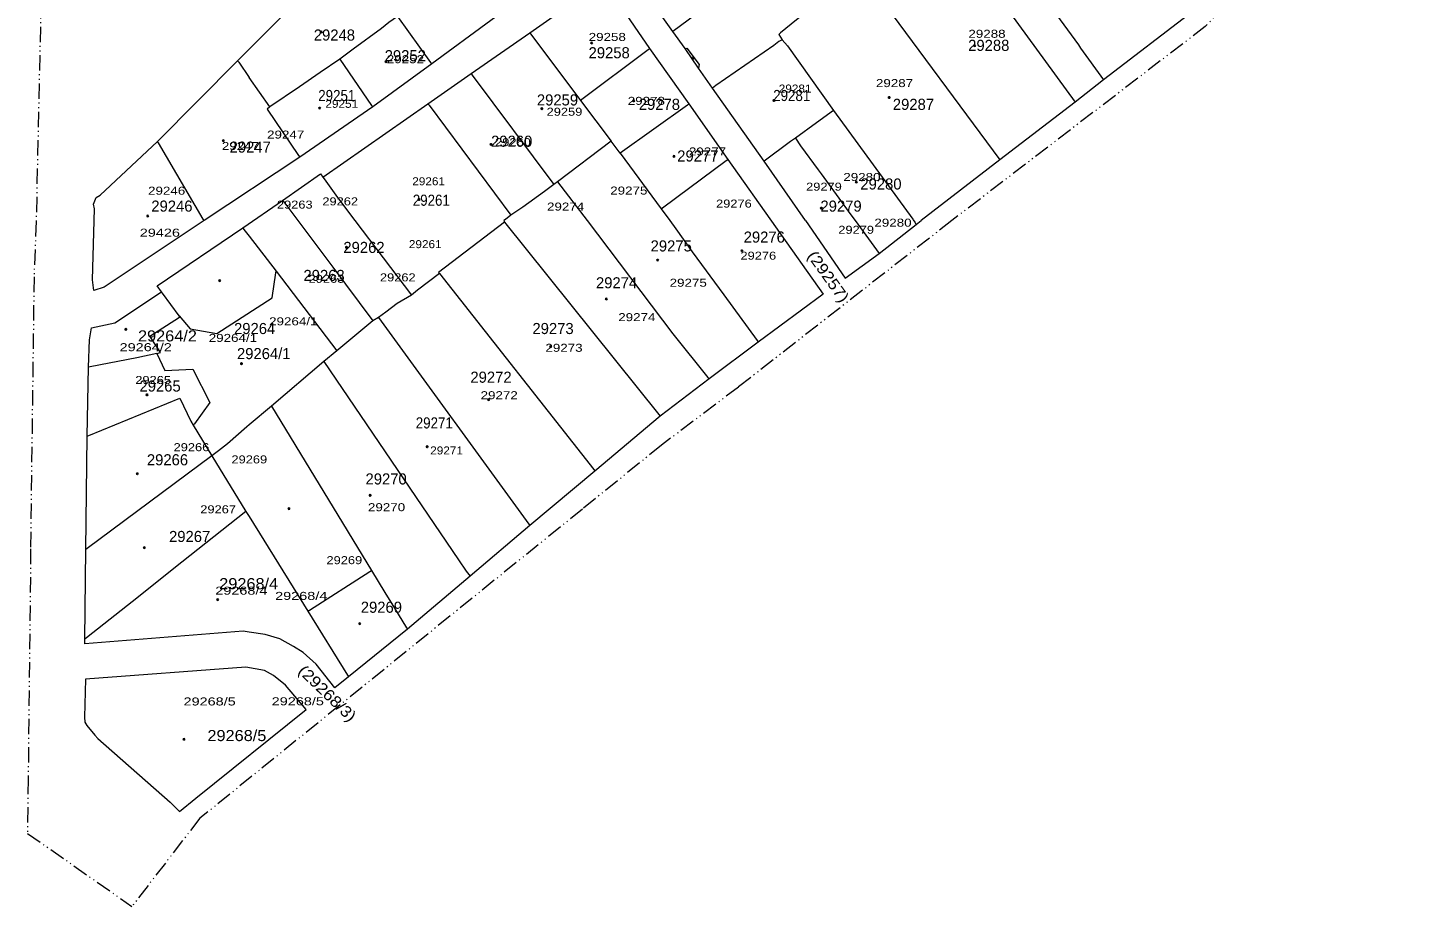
# Model space of a CAD drawing. Extents: x 650553 to 652508, y 239277 to 241647.
# Drawn here: x 650553 to 651000, y 239277.3 to 239562.7 of the extents above; entities that cross this region are included whole.
import ezdxf

# ---------------------------------------------------------------- set-up
doc = ezdxf.new("R2010")
doc.units = 0
doc.header["$PDMODE"] = 32
doc.header["$PDSIZE"] = 0.5
doc.linetypes.add('DASH_DOUBLE_DOT', pattern=[9.2, 5, -1.2, 0.3, -1.2, 0.3, -1.2])
for name, color, linetype in [('19', 7, 'Continuous'), ('20', 7, 'Continuous'), ('44', 7, 'Continuous'), ('6', 7, 'Continuous')]:
    doc.layers.add(name, color=color, linetype=linetype)
for name, color, linetype, lineweight in [('3', 7, 'Continuous', 13), ('5', 7, 'Continuous', 13), ('52', 7, 'DASH_DOUBLE_DOT', 13)]:
    doc.layers.add(name, color=color, linetype=linetype, lineweight=lineweight)

msp = doc.modelspace()

# ---------------------------------------------------------------- linework, layer by layer
at = {"layer": '3'}
msp.add_line((650770.98, 239549.48), (650766.66, 239555.85), dxfattribs=at)
for points in [[(650766.66, 239555.85), (650762.69, 239561.36), (650746.99, 239583.49), (650766.57, 239599.63), (650765.87, 239600.32), (650777.65, 239613.61), (650778.65, 239612.38), (650790.25, 239624.22), (650813.28, 239649.12), (650837.06, 239673.5), (650840.71, 239673.57), (650857.5, 239654.04), (650866.83, 239643.35), (650876.22, 239632.41), (650885.67, 239621.34), (650903.75, 239600.18), (650931.7, 239568.01), (650902.59, 239545.65), (650893.39, 239538.45), (650868.88, 239519.76), (650843.34, 239500)], [(650718.04, 239599.25), (650729.3, 239584.51), (650729.19, 239583.87), (650703.5, 239564.91), (650684.32, 239550.84), (650665.13, 239536.9), (650641.42, 239520.61), (650610.36, 239500)], [(650574.582, 239477.239), (650574.134, 239480.709), (650574.717, 239503.811), (650574.49, 239505.368), (650574.913, 239506.43), (650575.36, 239507.491), (650576.588, 239508.285), (650595.268, 239525.716), (650621.254, 239551.909), (650654.66, 239585.53)], [(650716.19, 239560.97), (650738.16, 239576.42), (650741.28, 239575.98), (650755.11, 239555.85), (650767.89, 239537.86), (650780.51, 239519.85), (650811.5, 239476.07)], [(650635.87, 239506.54), (650648.23, 239515.14), (650648.99, 239514.09), (650683.06, 239537.92), (650697.11, 239547.7), (650716.19, 239560.97)], [(650805.69, 239500), (650792.32, 239519.26), (650775.57, 239542.95), (650770.98, 239549.48)], [(650596.53, 239476.9), (650595.13, 239478.77), (650622.94, 239497.63), (650635.87, 239506.54)], [(650610.36, 239500), (650577.916, 239478.38), (650574.582, 239477.239)], [(650805.69, 239500), (650818.67, 239481.31), (650829.71, 239489.27), (650841.71, 239498.74), (650843.34, 239500)], [(650572.85, 239452.4), (650573.17, 239461.27), (650573.827, 239465.187), (650581.417, 239466.74), (650596.53, 239476.9)], [(650811.5, 239476.07), (650790.35, 239460.51), (650774.42, 239448.55), (650758.49, 239436.51), (650737.35, 239418.67), (650716.22, 239400.93), (650696.77, 239384.52), (650676.41, 239367.3), (650657.3, 239351.86)], [(650657.3, 239351.86), (650652.84, 239348.24), (650646.78, 239355.91), (650642.52, 239359.72), (650639.36, 239361.66), (650635, 239364.16), (650630.24, 239365.64), (650625, 239366.37), (650623.07, 239366.64), (650571.62, 239362.51), (650571.63, 239364.07), (650571.93, 239393.18), (650572.42, 239429.99), (650572.85, 239452.4)], [(650643.51, 239341.28), (650636.83, 239349.19), (650632.92, 239352.23), (650629.96, 239353.91), (650623.98, 239354.96), (650571.791, 239351.034), (650571.564, 239338.794), (650571.637, 239337.113), (650572.328, 239336.032), (650574.908, 239332.935), (650575.851, 239331.85), (650599.36, 239311.1), (650602.39, 239308.17)], [(650602.39, 239308.17), (650607.67, 239312.43), (650643.51, 239341.28)]]:
    msp.add_lwpolyline(points, dxfattribs=at)
at = {"layer": '44'}
for p in [(650769.205, 239552.72), (650615.459, 239480.472)]:
    msp.add_point(p, dxfattribs=at)
at = {"layer": '5'}
for p, q in [((650631.74, 239536.94), (650625, 239546.48)), ((650725.21, 239512.58), (650734.76, 239500)), ((650659.31, 239500), (650677.69, 239475.75)), ((650734.76, 239500), (650762.68, 239463.25)), ((650821.84, 239500), (650829.71, 239489.27)), ((650594.99, 239456.85), (650588.53, 239455.44)), ((650625, 239403.91), (650644.065, 239373.187))]:
    msp.add_line(p, q, dxfattribs=at)
for points in [[(650813.28, 239649.12), (650825.35, 239632.21), (650829.08, 239627.18), (650836.27, 239617.04), (650844.45, 239605.56), (650852.96, 239593.81), (650855.66, 239590.17), (650893.39, 239538.45)], [(650790.25, 239624.22), (650808.99, 239600.06), (650816.68, 239590.35), (650822.43, 239582.83), (650823.49, 239581.14), (650828, 239575.1), (650829.56, 239572.82), (650868.88, 239519.76)], [(650718.04, 239599.25), (650717.54, 239598.88), (650707.71, 239591.61), (650697.46, 239584.18), (650692.22, 239580.3), (650686.94, 239576.22), (650677.82, 239569.6), (650673.19, 239566.23), (650670.35, 239564.25), (650667.97, 239562.39), (650658.79, 239555.61), (650654.51, 239552.4), (650648.09, 239548.02), (650641.32, 239543.45), (650631.74, 239536.94), (650630.85, 239536.19)], [(650766.57, 239599.63), (650782.34, 239579.46), (650784.15, 239577.16), (650781.87, 239575.48), (650770.15, 239566.89), (650762.69, 239561.36)], [(650861.68, 239601.04), (650864.89, 239596.76), (650875.8, 239582.61), (650878.61, 239578.67), (650894.41, 239557), (650895.06, 239556.01), (650902.59, 239545.65)], [(650810.56, 239571.23), (650802.8, 239565.19), (650797.62, 239560.92), (650797.03, 239560.44), (650798.19, 239558.67), (650799.89, 239556.69), (650814.88, 239535.76)], [(650673.19, 239566.23), (650683.958, 239551.34), (650684.32, 239550.84)], [(650716.19, 239560.97), (650716.562, 239560.47), (650732.59, 239538.94), (650742.6, 239525.75)], [(650798.19, 239558.67), (650797.04, 239558.13), (650795.4, 239556.86), (650776.64, 239543.89), (650775.57, 239542.95)], [(650755.11, 239555.85), (650754.61, 239555.475), (650732.59, 239538.94)], [(650766.66, 239555.85), (650767.17, 239555.96), (650771.19, 239550.66), (650770.98, 239549.48)], [(650621.254, 239551.909), (650621.599, 239551.409), (650625, 239546.48)], [(650654.51, 239552.4), (650664.787, 239537.4), (650665.13, 239536.9)], [(650697.11, 239547.7), (650697.483, 239547.2), (650723.93, 239511.71)], [(650630.85, 239536.19), (650641.081, 239521.11), (650641.42, 239520.61)], [(650683.06, 239537.92), (650683.432, 239537.42), (650710.01, 239501.72)], [(650767.89, 239537.86), (650767.39, 239537.503), (650745.52, 239521.87), (650742.6, 239525.75), (650725.21, 239512.58), (650723.93, 239511.71), (650720.93, 239509.44), (650713.89, 239504.37), (650710.01, 239501.72)], [(650814.88, 239535.76), (650809.34, 239531.74), (650802.46, 239526.72), (650800.83, 239525.66), (650792.32, 239519.26)], [(650814.88, 239535.76), (650840.556, 239500.5), (650840.751, 239500.233)], [(650802.46, 239526.72), (650804.14, 239524.28), (650809.81, 239516.44), (650810.78, 239515.21), (650816.56, 239507.23), (650820.13, 239502.34), (650821.84, 239500)], [(650610.36, 239500), (650610.067, 239500.5), (650595.561, 239525.216), (650595.268, 239525.716)], [(650745.52, 239521.87), (650758.89, 239503.84), (650761.68, 239500)], [(650771.94, 239513.59), (650780.01, 239519.485), (650780.51, 239519.85)], [(650648.99, 239514.09), (650649.342, 239513.59), (650653.66, 239507.46), (650659.31, 239500)], [(650758.89, 239503.84), (650763.97, 239507.59), (650771.94, 239513.59)], [(650635.87, 239506.54), (650636.247, 239506.04), (650640.8, 239500)], [(650640.8, 239500), (650652.19, 239484.89), (650656.33, 239479.33), (650665.23, 239467.44)], [(650710.01, 239501.72), (650708.26, 239500.382), (650707.776, 239500.012)], [(650707.776, 239500.012), (650707.94, 239499.5), (650707.95, 239499.47)], [(650761.68, 239500), (650763.64, 239497.29), (650768.89, 239489.81), (650779.26, 239475.88)], [(650840.751, 239500.233), (650841.221, 239499.5), (650841.71, 239498.74)], [(650622.94, 239497.63), (650623.323, 239497.13), (650625, 239494.94)], [(650707.95, 239499.47), (650686.48, 239483.18), (650686.89, 239482.76)], [(650707.95, 239499.47), (650758.089, 239437.01), (650758.49, 239436.51)], [(650625, 239494.94), (650633.731, 239483.516), (650653.5, 239457.65)], [(650602.3, 239469.05), (650605.851, 239464.833), (650614.529, 239463.314), (650632.456, 239474.954), (650633.657, 239483.016), (650633.731, 239483.516)], [(650686.89, 239482.76), (650679.67, 239477.35), (650677.69, 239475.75), (650673.14, 239473.01), (650669.37, 239470.2), (650667.02, 239468.57), (650665.23, 239467.44), (650653.5, 239457.65), (650649.27, 239454.24), (650632.26, 239439.7), (650625, 239433.62)], [(650686.89, 239482.76), (650736.956, 239419.17), (650737.35, 239418.67)], [(650602.3, 239469.05), (650596.898, 239476.4), (650596.53, 239476.9)], [(650779.26, 239475.88), (650789.989, 239461.01), (650790.35, 239460.51)], [(650594.99, 239456.85), (650596.21, 239457.15), (650592.76, 239462.45), (650602.34, 239468.65), (650602.3, 239469.05)], [(650667.02, 239468.57), (650715.856, 239401.43), (650716.22, 239400.93)], [(650762.68, 239463.25), (650774.021, 239449.05), (650774.42, 239448.55)], [(650588.53, 239455.44), (650573.35, 239452.497), (650572.85, 239452.4)], [(650594.99, 239456.85), (650597.643, 239451.358), (650606.747, 239451.709), (650612.236, 239440.901), (650607.224, 239434.009), (650606.86, 239433.509)], [(650649.27, 239454.24), (650692.98, 239389.82), (650695.55, 239386.13)], [(650572.42, 239429.99), (650572.92, 239430.196), (650602.48, 239442.37), (650606.04, 239434.86), (650606.86, 239433.509), (650612.9, 239423.56)], [(650632.26, 239439.7), (650664.712, 239386.401), (650669.09, 239379.21), (650671.07, 239376.08)], [(650625, 239433.62), (650624.3, 239433.03), (650617.98, 239427.54), (650615.06, 239425.26), (650612.9, 239423.56)], [(650612.9, 239423.56), (650572.43, 239393.551), (650571.93, 239393.18)], [(650612.9, 239423.56), (650623.98, 239405.55), (650625, 239403.91)], [(650623.98, 239405.55), (650600.59, 239387.02), (650589.01, 239377.84)], [(650644.065, 239373.187), (650644.565, 239373.507), (650664.212, 239386.081), (650664.712, 239386.401)], [(650695.55, 239386.13), (650696.391, 239385.02), (650696.77, 239384.52)], [(650589.01, 239377.84), (650572.13, 239364.466), (650571.63, 239364.07)], [(650671.07, 239376.08), (650676.106, 239367.8), (650676.41, 239367.3)], [(650644.065, 239373.187), (650656.99, 239352.36), (650657.3, 239351.86)]]:
    msp.add_lwpolyline(points, dxfattribs=at)
at = {"layer": '52'}
for points in [[(650605.404, 240765.589), (650575.102, 240622.376), (650564.111, 240019.547), (650563.292, 239912.239), (650561.967, 239831.306), (650558.948, 239635.138), (650557.76, 239590.469), (650555.824, 239499.761), (650555.114, 239481.758), (650553.994, 239393.396), (650554.019, 239393.395), (650553.222, 239318.763), (650553.006, 239301.006), (650586.911, 239277.281)], [(650999.992, 239629.999), (650935.614, 239563.008), (650853.248, 239499.982)], [(650853.248, 239499.982), (650783.945, 239445.947), (650758.972, 239427.067), (650733.25, 239406.304), (650609.023, 239305.936), (650586.911, 239277.281)]]:
    msp.add_lwpolyline(points, dxfattribs=at)
at = {"layer": '6'}
for p in [(650648.463, 239561.235), (650736.246, 239557.68), (650860.729, 239556.785), (650669.439, 239551.565), (650769.205, 239552.72), (650832.906, 239539.94), (650647.889, 239536.505), (650720.069, 239536.34), (650749.915, 239538.86), (650795.486, 239538.965), (650616.649, 239525.954), (650703.568, 239524.71), (650763.043, 239520.85), (650822.269, 239512.515), (650680.168, 239506.835), (650810.905, 239504.015), (650592.076, 239501.477), (650656.639, 239491.29), (650757.696, 239487.15), (650785.071, 239490.18), (650644.544, 239482.095), (650615.459, 239480.472), (650741.029, 239474.545), (650584.948, 239464.65), (650722.961, 239459.07), (650622.519, 239453.538), (650591.817, 239443.42), (650702.781, 239441.845), (650682.825, 239426.545), (650588.678, 239417.775), (650664.32, 239410.77), (650637.97, 239406.443), (650590.977, 239393.815), (650614.791, 239376.895), (650660.94, 239369.13), (650603.808, 239331.565)]:
    msp.add_point(p, dxfattribs=at)

# ---------------------------------------------------------------- texts
at = {"layer": '19'}
for s, p in [('29248', (650646.007, 239558.435)), ('29288', (650858.581, 239555.083)), ('29252', (650669.042, 239551.731)), ('29258', (650735.264, 239552.689)), ('29259', (650718.469, 239537.366)), ('29278', (650751.581, 239535.929)), ('29287', (650834.107, 239535.929)), ('29260', (650703.593, 239523.957)), ('29247', (650618.655, 239522.042)), ('29277', (650764.058, 239519.169)), ('29280', (650823.549, 239510.07)), ('29246', (650593.222, 239502.888)), ('29279', (650810.592, 239502.887)), ('29276', (650785.652, 239492.831)), ('29262', (650655.605, 239489.48)), ('29275', (650755.42, 239489.958)), ('29263', (650642.649, 239480.381)), ('29274', (650737.665, 239477.987)), ('29264', (650620.095, 239463.142)), ('29273', (650717.03, 239463.142)), ('29264/1', (650621.043, 239454.999)), ('29272', (650696.876, 239447.34)), ('29265', (650589.383, 239444.466)), ('29266', (650591.782, 239420.523)), ('29270', (650662.805, 239414.299)), ('29267', (650598.98, 239395.622)), ('29269', (650661.27, 239372.644))]:
    msp.add_text(s, height=3.6, dxfattribs=at).set_placement(p)
for s, width, p in [('29251', 0.9, (650647.448, 239538.802)), ('29281', 0.9, (650795.237, 239538.802)), ('29261', 0.9, (650678.159, 239504.803)), ('29264/2', 1.1, (650588.891, 239460.746)), ('29271', 0.9, (650679.121, 239432.495)), ('29268/4', 1.1, (650615.284, 239380.297)), ('29268/5', 1.1, (650611.445, 239330.975))]:
    msp.add_text(s, height=3.6, dxfattribs=dict(at, width=width)).set_placement(p)
at = {"layer": '19', "width": 1.15}
for s, rotation, p in [('(29257)', 305.55, (650806.134, 239488.528)), ('(29268/3)', 315.992, (650640.628, 239353.432))]:
    msp.add_text(s, height=3.6, rotation=rotation, dxfattribs=at).set_placement(p)
at = {"layer": '20'}
for s, width, p in [('29258', 1.25, (650735.296, 239558.322)), ('29288', 1.25, (650858.65, 239559.34)), ('29252', 1.25, (650669.725, 239551.084)), ('29287', 1.25, (650828.614, 239543.33)), ('29278', 1.25, (650747.996, 239537.564)), ('29281', 1.1, (650797.046, 239541.554)), ('29251', 1.1, (650649.769, 239536.6)), ('29259', 1.2, (650721.636, 239534.027)), ('29247', 1.25, (650630.83, 239526.614)), ('29260', 1.2, (650704.905, 239524.139)), ('29247', 1.25, (650616.138, 239522.897)), ('29277', 1.25, (650767.865, 239521.126)), ('29261', 1.1, (650677.989, 239511.448)), ('29280', 1.25, (650818.021, 239512.827)), ('29246', 1.25, (650592.161, 239508.387)), ('29275', 1.25, (650742.301, 239508.435)), ('29279', 1.2, (650805.927, 239509.696)), ('29263', 1.2, (650634.018, 239503.874)), ('29262', 1.2, (650648.78, 239504.921)), ('29274', 1.25, (650721.764, 239503.238)), ('29276', 1.2, (650776.673, 239504.205)), ('29280', 1.25, (650828.109, 239498)), ('29426 ', 1.35, (650589.467, 239494.756)), ('29279', 1.2, (650816.387, 239495.703)), ('29261', 1.1, (650676.886, 239491.035)), ('29276', 1.2, (650784.604, 239487.29)), ('29263', 1.2, (650644.321, 239479.784)), ('29262', 1.2, (650667.492, 239480.241)), ('29275', 1.25, (650761.593, 239478.507)), ('29264/1', 1.25, (650631.486, 239465.969)), ('29274', 1.25, (650744.908, 239467.331)), ('29264/2', 1.35, (650582.918, 239457.579)), ('29264/1', 1.25, (650611.879, 239460.589)), ('29273', 1.25, (650721.242, 239457.381)), ('29265', 1.2, (650588.017, 239446.929)), ('29272', 1.25, (650700.189, 239441.985)), ('29266', 1.2, (650600.459, 239425.112)), ('29269', 1.2, (650619.252, 239421.139)), ('29271', 1.1, (650683.822, 239424.053)), ('29267', 1.2, (650609.126, 239404.936)), ('29270', 1.25, (650663.598, 239405.622)), ('29269', 1.2, (650650.129, 239388.422)), ('29268/4', 1.35, (650613.985, 239378.525)), ('29268/4', 1.35, (650633.44, 239376.823)), ('29268/5', 1.35, (650603.683, 239342.546)), ('29268/5', 1.35, (650632.328, 239342.606))]:
    msp.add_text(s, height=2.6, dxfattribs=dict(at, width=width)).set_placement(p)

doc.saveas('drawing.dxf')
